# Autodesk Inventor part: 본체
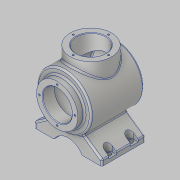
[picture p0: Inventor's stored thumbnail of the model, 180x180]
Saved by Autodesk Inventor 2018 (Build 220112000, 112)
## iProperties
Created: 2021-04
Part Number: 본체
Material: 알루미늄 6061
Document SubType Name: Modeling
Designer: home
Density: 2.7 g/cm^3
Appearance: 알루미늄 - 평지
Mass: 1640.61 g
Surface Area: 1041.98 cm^2
Volume: 607.632 cm^3
Author: home
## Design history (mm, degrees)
sketch "스케치2"
  geometry: L1 (77, 20)-(77, -100); L2 (104, 20)-(115, 20); L3 (115, 20)-(115, 11); L4 (118, 8)-(124, 8); L5 (127, 5)-(127, -86.454); L6 (104, 20)-(104, -2); L7 (104, -2)-(117, -2); L8 (117, -2)-(117, -79.903); A1 r 113 centre (77, 13) between (77, -100) and (125.282, -89.166); A2 r 3 centre (124, -86.454) between (125.282, -89.166) and (127, -86.454); A3 r 3 centre (124, 5) between (127, 5) and (124, 8); A4 r 3 centre (118, 11) between (115, 11) and (118, 8); A5 r 103 centre (77, 13) between (77, -90) and (115.11, -82.69); A6 r 3 centre (114, -79.903) between (115.11, -82.69) and (117, -79.903); 3 further points
  constraints: 16 end point, 14 point on circle, 8 tangent, 6 centre point, 5 perpendicular, 3 point on line, 2 vertical, 1 equal radius, 1 horizontal, 1 horizontal alignment, 1 vertical alignment
  dimensions: "d2" = 77 distance from line of L1 point (0, 0); "d3" = 20 vertical distance of point (0, 0) L1.start; "d4" = 76 diameter of L3 L1; "d5" = 100 diameter of L5 L1; "d6" = 12 distance between parallel lines of L4 L2; "d7" = 226 diameter of A1; "d8" = 108 distance from line of L1.end L4; "d9" = 3 radius of A2; "d10" = 3 radius of A3 (derived); "d11" = 10 radial gap between concentric circles of A1 A5; "d12" = 54 diameter of L6 L1; "d13" = 80 diameter of L8 L1; "d14" = 22 distance between parallel lines of L7 L2; "d15" = 3 radius of A6 (derived)
revolve "회전1" sketch "스케치2" stored, may be unused: angle "d16" = 90 deg
node "작업 평면1"
sketch "스케치3"
  geometry: L1 (-38, 20)-(38, 20) reference; C1 r 38 at (0, -42); 1 further point
  constraints: 1 centre point, 1 vertical alignment
  dimensions: "d18" = 76 diameter of C1; "d19" = 62 distance from line of C1.centre L1
extrude "돌출1" join sketch "스케치3" stored distance "d20" = 10; taper "d21" = 0 deg
hole "구멍1" diameter "d24" = 54; stored, may be unused: countersink angle "d28" = 90 deg, drill point angle "d30" = 118 deg; dims "d22" = 10, "d23" = 10, "d25" = 6, "d26" = 4, "d27" = 2, "d29" = 51.5
sketch "스케치4"
  geometry: C1 r 38 at (0, 0) reference; C2 r 27 at (0, 0) reference; 2 further points
  constraints: 1 vertical alignment
  dimensions: "d31" = 32.5 distance of point (0, 32.5) C1.centre
hole "구멍2" sketch "스케치4" at (0, 32.5) diameter "d32" = 3.242; stored, may be unused: countersink angle "d36" = 90 deg, drill point angle "d38" = 118 deg; dims "d33" = 8, "d34" = 4, "d35" = 2, "d37" = 10
sketch "스케치5"
  geometry: C1 r 27 at (0, 0) reference; C2 r 38 at (0, 0) reference; 2 further points
  constraints: 1 horizontal alignment
  dimensions: "d42" = 32.5 distance of point (-32.5, 0) C1.centre
hole "구멍3" sketch "스케치5" at (-32.5, 0) diameter "d43" = 3.242; stored, may be unused: countersink angle "d47" = 90 deg, drill point angle "d49" = 118 deg; dims "d44" = 8, "d45" = 4, "d46" = 2, "d48" = 10
node "작업 평면4"
sketch "스케치7"
  geometry: L1 (-62, -77)-(-62, -67); L2 (-62, -67)-(-26.694, -42.278); L3 (-62, -67)-(-18.899, -67); L4 (-62, -77)-(-25.981, -77); L5 (25.981, -77)-(62, -77); L6 (62, -77)-(62, -67); L7 (62, -67)-(105.101, -67); L8 (62, -67)-(26.694, -42.278); L9 (62, -67)-(105.101, -67); A1 r 50 centre (0, 0) between (-26.694, -42.278) and (26.694, -42.278) reference; A2 r 30 centre (0, -92) between (25.981, -77) and (-25.981, -77); A3 r 50 centre (0, 0) between (-26.694, -42.278) and (26.694, -42.278); 3 further points
  constraints: 18 end point, 7 point on circle, 5 horizontal, 2 centre point, 2 coincident, 2 equal length, 2 horizontal alignment, 2 vertical, 2 vertical alignment, 1 concentric
  dimensions: "d56" = 124 distance of L1.start L5.end; "d57" = 10 distance of L1.start L1.end; "d58" = 35 deg angle of L3 L2; "d59" = 60 diameter of A2; "d61" = 15 distance of point (0, -62) point (0, -77); "d62" = 62 distance from line of point (0, -77) L1; "d64" = 145 deg angle of L9 L8; "d65" = 10 distance of L5.end L6.end
extrude "돌출2" join sketch "스케치7" distance "d66" = 80; taper "d67" = 0 deg
node "작업 평면5"
sketch "스케치8"
  geometry: L1 (-25.981, 0)-(-62, 0) reference; L2 (-25.981, 0)-(-25.981, -80) reference; L3 (-62, -80)-(-25.981, -80) reference; L4 (-62, 0)-(-62, -80) reference; L5 (-54, -53)-(-62, -53); L6 (-54, -67)-(-62, -67); L7 (-62, -53)-(-62, -67); A1 r 7 centre (-54, -60) between (-54, -67) and (-54, -53); 1 further point
  constraints: 6 end point, 2 perpendicular, 2 point on circle, 2 point on line, 2 tangent, 1 centre point, 1 collinear
  dimensions: "d69" = 14 diameter of A1; "d70" = 20 distance from line of A1.centre L3; "d71" = 8 distance from line of A1.centre L4
extrude "돌출3" cut sketch "스케치8" distance "d72" = 28.75; taper "d73" = 0 deg
sketch "스케치9"
  geometry: L1 (8, 40)-(0, 40) reference; L2 (0, 54)-(8, 54) reference; L3 (0, 40)-(0, 54) reference; L4 (8, 0)-(0, 0) reference; L5 (0, 14)-(8, 14) reference; L6 (0, 0)-(0, 14) reference; L7 (116, 40)-(124, 40) reference; L8 (124, 54)-(124, 40) reference; L9 (124, 54)-(116, 54) reference; L10 (116, 0)-(124, 0) reference; L11 (124, 14)-(124, 0) reference; L12 (124, 14)-(116, 14) reference; A1 r 7 centre (8, 47) between (8, 40) and (8, 54) reference; A2 r 7 centre (8, 7) between (8, 0) and (8, 14) reference; A3 r 7 centre (116, 47) between (116, 54) and (116, 40) reference; A4 r 7 centre (116, 7) between (116, 14) and (116, 0) reference; 1 further point
hole "구멍4" sketch "스케치9" at (8, 7), (8, 47), (116, 47), (116, 7) diameter "d77" = 9; stored, may be unused: countersink angle "d81" = 90 deg, drill point angle "d83" = 118 deg; dims "d78" = 8, "d79" = 4, "d80" = 2, "d82" = 10
chamfer "모따기1" distance "d84" = 1; stored, may be unused: second distance "d85" = 2, angle "d86" = 45 deg
fillet "모깎기1" dims "d87" = 3
node "작업 평면9"
node "작업 평면10"
sketch "스케치13"
  geometry: L1 (-38, 65)-(38, 65) reference; 2 further points
  constraints: 1 vertical alignment, 1 other
  dimensions: "d96" = 77 distance of point (0, 0) point (0, -77)
feature "엠보싱2" sketch "스케치13" dims "d97" = 0.5, "d98" = 0
node "솔리드1"
pattern_circular "원형 패턴1" dims angle "d40" = 360 deg
pattern_circular "원형 패턴2" dims angle "d51" = 360 deg
pattern_linear "직사각형 패턴1" dims "d76" = 40
mirror "미러1"
node "투영된 루프1"
node "투영된 루프2"
node "투영된 루프3"
node "투영된 루프4"
node "투영된 루프5"
node "투영된 루프6"
node "투영된 루프7"
other parameters: "d17" = 142, "d60" = 15, "d68" = 6, "d90" = -120.5, "d94" = 197.25
